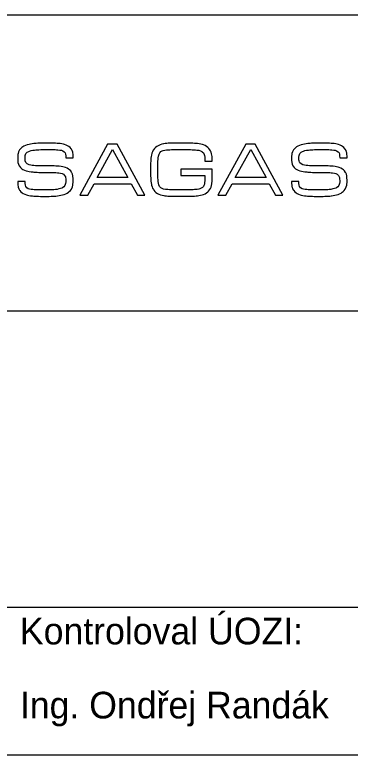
# Model space of a CAD drawing. Extents: x 70 to 433, y -123 to 195.
# Drawn here: x 221.2 to 243.8, y -21 to 29 of the extents above; entities that cross this region are included whole.
import ezdxf

# ---------------------------------------------------------------- set-up
doc = ezdxf.new("R2010")
doc.units = 0
doc.layers.add('SO 11-10-01_popisove_pole', color=7, linetype='Continuous')
doc.layers.add('Vrstva 63', color=7, linetype='Continuous')

# ---------------------------------------------------------------- blocks, each defined once
blk = doc.blocks.new('sagasta-logo')
at = {"layer": 'SO 11-10-01_popisove_pole'}
for points in [[(-0.604, -0.144), (-0.605, -0.121), (-0.607, -0.098), (-0.608, -0.09), (-0.613, -0.068), (-0.622, -0.048), (-0.625, -0.042), (-0.637, -0.023), (-0.654, -0.007), (-0.667, 0.003), (-0.686, 0.013), (-0.709, 0.023), (-0.724, 0.027), (-0.745, 0.032), (-0.767, 0.037), (-0.792, 0.04), (-0.796, 0.04), (-0.816, 0.042), (-0.837, 0.044), (-0.859, 0.045), (-0.883, 0.046), (-0.908, 0.046), (-1.02, 0.046), (-1.025, 0.046), (-1.051, 0.046), (-1.074, 0.046), (-1.095, 0.047), (-1.114, 0.048), (-1.136, 0.05), (-1.158, 0.052), (-1.178, 0.056), (-1.201, 0.062), (-1.224, 0.072), (-1.244, 0.091), (-1.253, 0.115), (-1.254, 0.129), (-1.255, 0.152), (-1.255, 0.165), (-1.251, 0.188), (-1.243, 0.211), (-1.226, 0.229), (-1.205, 0.241), (-1.193, 0.246), (-1.174, 0.252), (-1.151, 0.256), (-1.125, 0.26), (-1.108, 0.262), (-1.088, 0.263), (-1.067, 0.264), (-1.043, 0.265), (-1.019, 0.266), (-0.993, 0.266), (-0.911, 0.266), (-0.897, 0.266), (-0.872, 0.266), (-0.849, 0.265), (-0.829, 0.264), (-0.81, 0.263), (-0.785, 0.26), (-0.763, 0.256), (-0.745, 0.25), (-0.725, 0.237), (-0.713, 0.22), (-0.707, 0.204), (-0.704, 0.182), (-0.703, 0.154), (-0.604, 0.154), (-0.604, 0.179), (-0.606, 0.202), (-0.609, 0.222), (-0.61, 0.23), (-0.618, 0.252), (-0.628, 0.271), (-0.633, 0.278), (-0.647, 0.294), (-0.665, 0.309), (-0.68, 0.317), (-0.7, 0.326), (-0.722, 0.334), (-0.736, 0.338), (-0.757, 0.342), (-0.779, 0.346), (-0.803, 0.349), (-0.82, 0.35), (-0.842, 0.352), (-0.864, 0.353), (-0.887, 0.353), (-0.911, 0.354), (-0.993, 0.354), (-1.014, 0.354), (-1.038, 0.353), (-1.061, 0.352), (-1.083, 0.351), (-1.103, 0.35), (-1.123, 0.348), (-1.134, 0.347), (-1.158, 0.344), (-1.18, 0.34), (-1.201, 0.336), (-1.22, 0.33), (-1.226, 0.329), (-1.249, 0.321), (-1.269, 0.312), (-1.286, 0.302), (-1.298, 0.294), (-1.314, 0.278), (-1.328, 0.262), (-1.333, 0.254), (-1.342, 0.234), (-1.349, 0.212), (-1.351, 0.199), (-1.354, 0.176), (-1.354, 0.152), (-1.354, 0.141), (-1.353, 0.118), (-1.351, 0.096), (-1.35, 0.09), (-1.344, 0.068), (-1.335, 0.048), (-1.331, 0.041), (-1.318, 0.024), (-1.3, 0.008), (-1.283, -0.002), (-1.263, -0.012), (-1.24, -0.02), (-1.237, -0.021), (-1.218, -0.026), (-1.197, -0.03), (-1.174, -0.033), (-1.149, -0.036), (-1.134, -0.038), (-1.114, -0.04), (-1.092, -0.041), (-1.069, -0.042), (-1.045, -0.042), (-1.02, -0.042), (-0.908, -0.042), (-0.885, -0.042), (-0.861, -0.043), (-0.838, -0.044), (-0.818, -0.046), (-0.8, -0.048), (-0.776, -0.053), (-0.754, -0.059), (-0.737, -0.067), (-0.72, -0.082), (-0.709, -0.101), (-0.707, -0.11), (-0.704, -0.131), (-0.703, -0.156), (-0.703, -0.17), (-0.706, -0.193), (-0.715, -0.217), (-0.73, -0.236), (-0.749, -0.25), (-0.756, -0.253), (-0.775, -0.26), (-0.797, -0.266), (-0.822, -0.271), (-0.826, -0.272), (-0.845, -0.274), (-0.866, -0.276), (-0.888, -0.277), (-0.912, -0.278), (-0.938, -0.278), (-1.047, -0.278), (-1.063, -0.278), (-1.088, -0.278), (-1.11, -0.277), (-1.131, -0.276), (-1.149, -0.275), (-1.172, -0.273), (-1.194, -0.268), (-1.213, -0.262), (-1.232, -0.249), (-1.245, -0.231), (-1.25, -0.215), (-1.254, -0.193), (-1.255, -0.165), (-1.354, -0.165), (-1.353, -0.191), (-1.352, -0.214), (-1.349, -0.233), (-1.347, -0.241), (-1.34, -0.263), (-1.329, -0.282), (-1.325, -0.288), (-1.311, -0.305), (-1.293, -0.32), (-1.279, -0.329), (-1.258, -0.338), (-1.236, -0.346), (-1.223, -0.35), (-1.202, -0.354), (-1.179, -0.358), (-1.155, -0.361), (-1.138, -0.362), (-1.118, -0.364), (-1.095, -0.365), (-1.072, -0.365), (-1.047, -0.366), (-0.938, -0.366), (-0.928, -0.366), (-0.904, -0.365), (-0.881, -0.364), (-0.858, -0.363), (-0.838, -0.362), (-0.818, -0.36), (-0.792, -0.355), (-0.77, -0.351), (-0.749, -0.346), (-0.727, -0.339), (-0.705, -0.331), (-0.685, -0.321), (-0.668, -0.309), (-0.658, -0.301), (-0.642, -0.285), (-0.629, -0.268), (-0.624, -0.259), (-0.615, -0.238), (-0.609, -0.216), (-0.607, -0.202), (-0.604, -0.18), (-0.604, -0.156), (-0.604, -0.144)], [(-0.012, 0.339), (-0.139, 0.339), (-0.515, -0.351), (-0.406, -0.351), (-0.322, -0.197), (0.179, -0.197), (0.263, -0.351), (0.363, -0.351), (-0.012, 0.339)], [(0.556, 0.205), (0.565, 0.223), (0.579, 0.238), (0.599, 0.249), (0.612, 0.254), (0.633, 0.259), (0.658, 0.262), (0.659, 0.262), (0.678, 0.263), (0.7, 0.264), (0.723, 0.265), (0.748, 0.265), (0.967, 0.265), (0.981, 0.265), (1.005, 0.264), (1.028, 0.263), (1.049, 0.262), (1.067, 0.26), (1.069, 0.26), (1.093, 0.256), (1.114, 0.25), (1.132, 0.242), (1.14, 0.236), (1.155, 0.22), (1.165, 0.199), (1.169, 0.184), (1.173, 0.164), (1.175, 0.139), (1.175, 0.111), (1.274, 0.111), (1.274, 0.125), (1.274, 0.149), (1.272, 0.172), (1.269, 0.191), (1.266, 0.208), (1.259, 0.23), (1.25, 0.25), (1.243, 0.263), (1.23, 0.28), (1.214, 0.296), (1.197, 0.308), (1.178, 0.319), (1.156, 0.328), (1.142, 0.333), (1.121, 0.338), (1.099, 0.343), (1.075, 0.346), (1.058, 0.349), (1.036, 0.35), (1.014, 0.352), (0.991, 0.353), (0.967, 0.353), (0.748, 0.353), (0.729, 0.353), (0.704, 0.352), (0.681, 0.351), (0.66, 0.349), (0.639, 0.346), (0.621, 0.343), (0.617, 0.343), (0.593, 0.337), (0.572, 0.33), (0.552, 0.323), (0.534, 0.313), (0.527, 0.309), (0.508, 0.296), (0.493, 0.28), (0.48, 0.263), (0.476, 0.257), (0.466, 0.237), (0.458, 0.216), (0.453, 0.192), (0.449, 0.173), (0.446, 0.151), (0.444, 0.128), (0.443, 0.103), (0.442, 0.087), (0.442, 0.065), (0.441, 0.042), (0.441, 0.019), (0.441, -0.006), (0.441, -0.025), (0.441, -0.049), (0.442, -0.072), (0.442, -0.094), (0.443, -0.115), (0.444, -0.139), (0.446, -0.162), (0.449, -0.184), (0.453, -0.205), (0.454, -0.213), (0.461, -0.235), (0.469, -0.256), (0.48, -0.275), (0.484, -0.282), (0.498, -0.298), (0.514, -0.313), (0.537, -0.328), (0.554, -0.336), (0.574, -0.344), (0.596, -0.35), (0.62, -0.355), (0.635, -0.358), (0.655, -0.36), (0.676, -0.362), (0.699, -0.364), (0.723, -0.365), (0.748, -0.365), (0.967, -0.365), (0.989, -0.365), (1.013, -0.364), (1.035, -0.363), (1.056, -0.361), (1.076, -0.359), (1.093, -0.356), (1.116, -0.352), (1.137, -0.346), (1.156, -0.34), (1.178, -0.33), (1.197, -0.319), (1.214, -0.306), (1.225, -0.295), (1.239, -0.278), (1.25, -0.258), (1.258, -0.24), (1.265, -0.219), (1.269, -0.195), (1.27, -0.187), (1.273, -0.166), (1.274, -0.142), (1.274, -0.118), (1.274, 0.003), (0.849, 0.003), (0.849, -0.085), (1.175, -0.085), (1.175, -0.118), (1.175, -0.133), (1.174, -0.157), (1.172, -0.178), (1.169, -0.2), (1.162, -0.22), (1.156, -0.231), (1.141, -0.248), (1.127, -0.257), (1.105, -0.265), (1.094, -0.268), (1.073, -0.272), (1.049, -0.274), (1.036, -0.275), (1.015, -0.276), (0.992, -0.277), (0.967, -0.277), (0.748, -0.277), (0.746, -0.277), (0.72, -0.277), (0.697, -0.276), (0.676, -0.275), (0.657, -0.274), (0.641, -0.272), (0.618, -0.267), (0.6, -0.261), (0.58, -0.25), (0.564, -0.234), (0.554, -0.212), (0.548, -0.187), (0.545, -0.165), (0.542, -0.142), (0.541, -0.117), (0.541, -0.102), (0.541, -0.081), (0.541, -0.058), (0.54, -0.033), (0.54, -0.006), (0.54, 0.018), (0.541, 0.043), (0.541, 0.066), (0.541, 0.087), (0.541, 0.105), (0.541, 0.108), (0.542, 0.133), (0.545, 0.156), (0.548, 0.179), (0.556, 0.205)], [(1.854, 0.339), (1.727, 0.339), (1.351, -0.351), (1.459, -0.351), (1.544, -0.197), (2.044, -0.197), (2.129, -0.351), (2.229, -0.351), (1.854, 0.339)], [(2.458, 0.089), (2.455, 0.094), (2.447, 0.115), (2.446, 0.129), (2.445, 0.152), (2.445, 0.165), (2.449, 0.188), (2.457, 0.211), (2.474, 0.229), (2.495, 0.241), (2.507, 0.246), (2.526, 0.252), (2.549, 0.256), (2.575, 0.26), (2.592, 0.262), (2.612, 0.263), (2.634, 0.264), (2.657, 0.265), (2.681, 0.266), (2.707, 0.266), (2.789, 0.266), (2.803, 0.266), (2.828, 0.266), (2.851, 0.265), (2.871, 0.264), (2.89, 0.263), (2.915, 0.26), (2.937, 0.256), (2.955, 0.25), (2.975, 0.237), (2.988, 0.22), (2.993, 0.204), (2.996, 0.182), (2.997, 0.154), (3.097, 0.154), (3.096, 0.179), (3.094, 0.202), (3.091, 0.222), (3.09, 0.23), (3.082, 0.252), (3.072, 0.271), (3.067, 0.278), (3.053, 0.294), (3.035, 0.309), (3.02, 0.317), (3.001, 0.326), (2.978, 0.334), (2.964, 0.338), (2.943, 0.342), (2.921, 0.346), (2.897, 0.349), (2.88, 0.35), (2.859, 0.352), (2.837, 0.353), (2.813, 0.353), (2.789, 0.354), (2.707, 0.354), (2.686, 0.354), (2.662, 0.353), (2.639, 0.352), (2.617, 0.351), (2.597, 0.35), (2.577, 0.348), (2.566, 0.347), (2.542, 0.344), (2.52, 0.34), (2.499, 0.336), (2.48, 0.33), (2.474, 0.329), (2.452, 0.321), (2.431, 0.312), (2.414, 0.302), (2.402, 0.294), (2.386, 0.278), (2.372, 0.262), (2.367, 0.254), (2.358, 0.234), (2.351, 0.212), (2.349, 0.199), (2.346, 0.176), (2.346, 0.152), (2.346, 0.141), (2.347, 0.118), (2.349, 0.096), (2.35, 0.09), (2.356, 0.068), (2.365, 0.048), (2.369, 0.041), (2.382, 0.024), (2.4, 0.008), (2.417, -0.002), (2.437, -0.012), (2.46, -0.02), (2.463, -0.021), (2.482, -0.026), (2.503, -0.03), (2.526, -0.033), (2.551, -0.036), (2.566, -0.038), (2.587, -0.04), (2.608, -0.041), (2.631, -0.042), (2.655, -0.042), (2.68, -0.042), (2.792, -0.042), (2.815, -0.042), (2.84, -0.043), (2.862, -0.044), (2.882, -0.046), (2.9, -0.048), (2.925, -0.053), (2.946, -0.059), (2.963, -0.067), (2.98, -0.082), (2.991, -0.101), (2.993, -0.11), (2.996, -0.131), (2.997, -0.156), (2.997, -0.17), (2.994, -0.193), (2.985, -0.217), (2.97, -0.236), (2.951, -0.25), (2.944, -0.253), (2.926, -0.26), (2.904, -0.266), (2.878, -0.271), (2.874, -0.272), (2.855, -0.274), (2.834, -0.276), (2.812, -0.277), (2.788, -0.278), (2.762, -0.278), (2.653, -0.278), (2.637, -0.278), (2.612, -0.278), (2.59, -0.277), (2.569, -0.276), (2.551, -0.275), (2.528, -0.273), (2.506, -0.268), (2.488, -0.262), (2.468, -0.249), (2.455, -0.231), (2.45, -0.215), (2.446, -0.193), (2.445, -0.165), (2.346, -0.165), (2.347, -0.191), (2.348, -0.214), (2.351, -0.233), (2.353, -0.241), (2.36, -0.263), (2.371, -0.282), (2.375, -0.288), (2.389, -0.305), (2.407, -0.32), (2.422, -0.329), (2.442, -0.338), (2.464, -0.346), (2.478, -0.35), (2.498, -0.354), (2.521, -0.358), (2.545, -0.361), (2.562, -0.362), (2.583, -0.364), (2.605, -0.365), (2.628, -0.365), (2.653, -0.366), (2.762, -0.366), (2.772, -0.366), (2.797, -0.365), (2.82, -0.364), (2.842, -0.363), (2.862, -0.362), (2.882, -0.36), (2.884, -0.359), (2.908, -0.355), (2.93, -0.351), (2.951, -0.346), (2.974, -0.339), (2.995, -0.331), (3.015, -0.321), (3.032, -0.309), (3.043, -0.301), (3.058, -0.285), (3.071, -0.268), (3.076, -0.259), (3.085, -0.238), (3.091, -0.216), (3.093, -0.202), (3.096, -0.18), (3.097, -0.156), (3.096, -0.144), (3.095, -0.121), (3.093, -0.098), (3.092, -0.09), (3.087, -0.068), (3.078, -0.048), (3.075, -0.042), (3.063, -0.023), (3.046, -0.007), (3.033, 0.003), (3.014, 0.013), (2.991, 0.023), (2.976, 0.027), (2.955, 0.032), (2.933, 0.037), (2.908, 0.04), (2.904, 0.04), (2.884, 0.042), (2.863, 0.044), (2.841, 0.045), (2.817, 0.046), (2.792, 0.046), (2.68, 0.046), (2.675, 0.046), (2.649, 0.046), (2.626, 0.046), (2.605, 0.047), (2.587, 0.048), (2.564, 0.05), (2.542, 0.052), (2.522, 0.056), (2.499, 0.062), (2.476, 0.072), (2.458, 0.089)], [(-0.071, 0.266), (0.136, -0.109), (-0.279, -0.109), (-0.071, 0.266)], [(1.795, 0.266), (2.002, -0.109), (1.586, -0.109), (1.795, 0.266)]]:
    blk.add_lwpolyline(points, dxfattribs=at)

msp = doc.modelspace()

# ---------------------------------------------------------------- linework, layer by layer
at = {"layer": 'SO 11-10-01_popisove_pole'}
for p, q in [((89.952, 8.954), (259.952, 8.954)), ((89.952, -11.046), (259.952, -11.046))]:
    msp.add_line(p, q, dxfattribs=at)
msp.add_lwpolyline([(89.952, 28.954), (259.952, 28.954), (259.952, -21.046), (89.952, -21.046)], close=True, dxfattribs=at)

# ---------------------------------------------------------------- block references
at = {"layer": 'SO 11-10-01_popisove_pole', "xscale": 4.999999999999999, "yscale": 4.999999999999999, "rotation": -1.310668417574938e-10}
msp.add_blockref('sagasta-logo', (228.151, 18.523), dxfattribs=at)

# ---------------------------------------------------------------- texts
at = {"layer": 'Vrstva 63'}
for s, p in [('Kontroloval ÚOZI:', (221.53, -13.563)), ('Ing. Ondřej Randák', (221.53, -18.563))]:
    msp.add_text(s, height=1.8, dxfattribs=at).set_placement(p)

doc.saveas('drawing.dxf')
